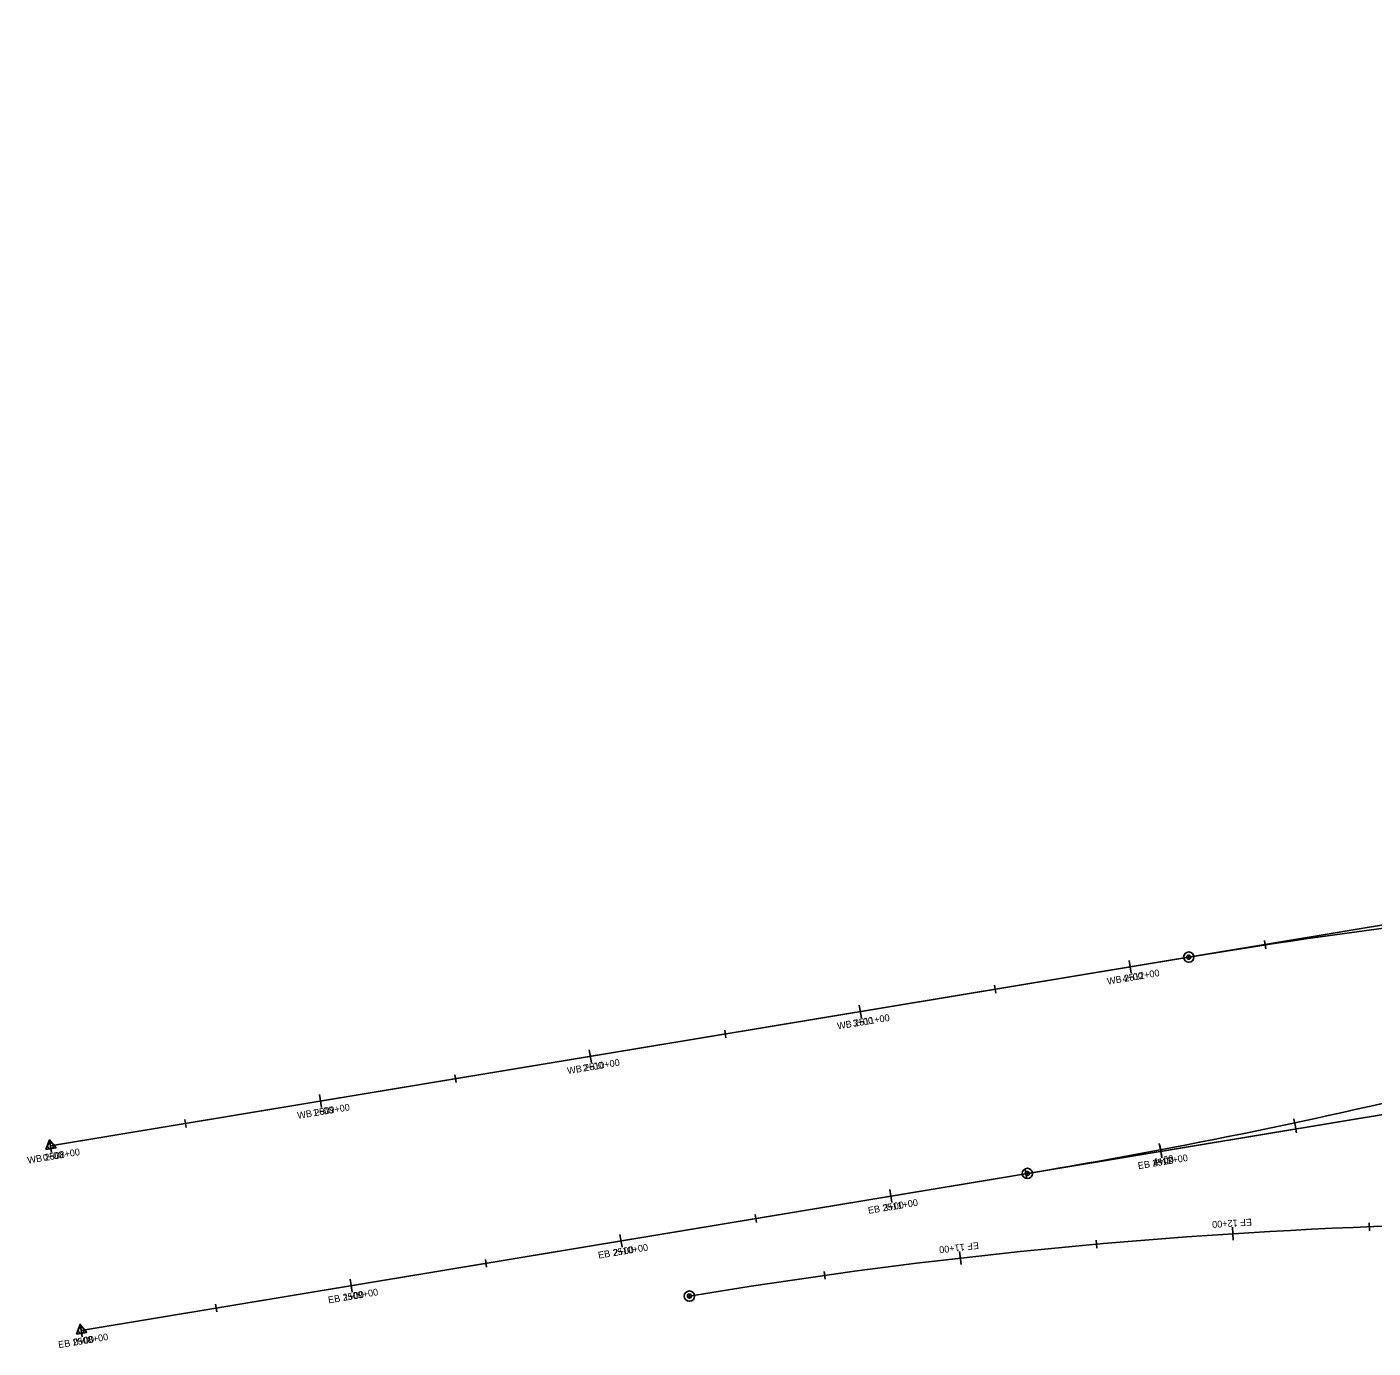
# Model space of a CAD drawing. Extents: x 950864 to 953360, y 1126381 to 1128045.
# Drawn here: x 950863.9 to 951355.9, y 1127047.3 to 1127530 of the extents above; entities that cross this region are included whole.
import ezdxf

# ---------------------------------------------------------------- set-up
doc = ezdxf.new("R2010")
doc.units = 0
for name, color, linetype in [('Existing', 7, 'Continuous'), ('LFILL_P', 7, 'Continuous'), ('North Crossover', 7, 'Continuous')]:
    doc.layers.add(name, color=color, linetype=linetype)

msp = doc.modelspace()

# ---------------------------------------------------------------- linework, layer by layer
at = {"layer": 'Existing'}
for p, q in [((950872.52, 1127121.15), (953338.85, 1127530.05)), ((950883.69, 1127053.72), (953350.03, 1127462.62))]:
    msp.add_line(p, q, dxfattribs=at)
for points in [[(951316.22, 1127196.17), (951316.69, 1127193.33)], [(951266.74, 1127188.94), (951267.52, 1127184.21)], [(951217.57, 1127179.82), (951218.04, 1127176.97)], [(951168.08, 1127172.59), (951168.87, 1127167.85)], [(951118.91, 1127163.46), (951119.38, 1127160.62)], [(951069.43, 1127156.23), (951070.21, 1127151.49)], [(951020.26, 1127147.1), (951020.73, 1127144.26)], [(950970.78, 1127139.87), (950971.56, 1127135.14)], [(950921.61, 1127130.75), (950922.08, 1127127.91)], [(951327.4, 1127128.74), (951327.87, 1127125.9)], [(950870.83, 1127119.76), (950872.16, 1127123.3)], [(950874.56, 1127120.38), (950870.83, 1127119.76)], [(950872.12, 1127123.52), (950872.91, 1127118.78)], [(950872.16, 1127123.3), (950874.56, 1127120.38)], [(951277.92, 1127121.51), (951278.7, 1127116.78)], [(951228.75, 1127112.39), (951229.22, 1127109.55)], [(951179.26, 1127105.16), (951180.05, 1127100.42)], [(951130.09, 1127096.03), (951130.56, 1127093.19)], [(951304.47, 1127091.42), (951304.77, 1127086.63)], [(951354.5, 1127093.03), (951354.61, 1127090.15)], [(951080.61, 1127088.8), (951081.39, 1127084.07)], [(951254.64, 1127086.63), (951254.9, 1127083.76)], [(951204.76, 1127082.51), (951205.3, 1127077.74)], [(951031.44, 1127079.68), (951031.91, 1127076.84)], [(950981.96, 1127072.45), (950982.74, 1127067.71)], [(951155.23, 1127075.24), (951155.63, 1127072.38)], [(950932.79, 1127063.32), (950933.26, 1127060.48)], [(950883.3, 1127056.09), (950884.09, 1127051.35)], [(950882.01, 1127052.33), (950883.34, 1127055.87)], [(950885.74, 1127052.95), (950882.01, 1127052.33)], [(950883.34, 1127055.87), (950885.74, 1127052.95)]]:
    msp.add_lwpolyline(points, dxfattribs=at)
for centre, radius in [((950872.52, 1127121.15), 1.09), ((951106.01, 1127066.25), 1.88), ((951106.01, 1127066.25), 0.747), ((951106.01, 1127066.25), 0.156), ((950883.7, 1127053.72), 1.09)]:
    msp.add_circle(centre, radius, dxfattribs=at)
msp.add_arc((951432.14, 1125099.1), 1994, 85.39079, 99.4135, dxfattribs=at)
at = {"layer": 'LFILL_P'}
for p, q in [((950872.52, 1127121.15), (951288.53, 1127190.12)), ((950883.69, 1127053.72), (951597.75, 1127172.11))]:
    msp.add_line(p, q, dxfattribs=at)
for points in [[(951316.27, 1127195.99), (951316.7, 1127193.14)], [(951266.74, 1127188.94), (951267.52, 1127184.21)], [(951217.57, 1127179.82), (951218.04, 1127176.97)], [(951168.08, 1127172.59), (951168.87, 1127167.85)], [(951118.91, 1127163.46), (951119.38, 1127160.62)], [(951069.43, 1127156.23), (951070.21, 1127151.49)], [(951020.26, 1127147.1), (951020.73, 1127144.26)], [(950970.78, 1127139.87), (950971.56, 1127135.14)], [(950921.61, 1127130.75), (950922.08, 1127127.91)], [(951327.4, 1127128.74), (951327.87, 1127125.9)], [(950870.83, 1127119.76), (950872.16, 1127123.3)], [(950874.56, 1127120.38), (950870.83, 1127119.76)], [(950872.12, 1127123.52), (950872.91, 1127118.78)], [(950872.16, 1127123.3), (950874.56, 1127120.38)], [(951277.92, 1127121.51), (951278.7, 1127116.78)], [(951228.75, 1127112.39), (951229.22, 1127109.55)], [(951179.26, 1127105.16), (951180.05, 1127100.42)], [(951130.09, 1127096.03), (951130.56, 1127093.19)], [(951080.61, 1127088.8), (951081.39, 1127084.07)], [(951031.44, 1127079.68), (951031.91, 1127076.84)], [(950981.96, 1127072.45), (950982.74, 1127067.71)], [(950932.79, 1127063.32), (950933.26, 1127060.48)], [(950883.3, 1127056.09), (950884.09, 1127051.35)], [(950882.01, 1127052.33), (950883.34, 1127055.87)], [(950885.74, 1127052.95), (950882.01, 1127052.33)], [(950883.34, 1127055.87), (950885.74, 1127052.95)]]:
    msp.add_lwpolyline(points, dxfattribs=at)
for centre, radius in [((951288.53, 1127190.12), 1.88), ((951288.53, 1127190.12), 0.747), ((951288.53, 1127190.12), 0.156), ((950872.52, 1127121.15), 1.09), ((950883.7, 1127053.72), 1.09)]:
    msp.add_circle(centre, radius, dxfattribs=at)
msp.add_arc((951642.63, 1125054.28), 2165, 90.26513, 99.4135, dxfattribs=at)
at = {"layer": 'North Crossover'}
for p, q in [((950872.52, 1127121.15), (951607.23, 1127242.96)), ((950883.69, 1127053.72), (951229.53, 1127111.06))]:
    msp.add_line(p, q, dxfattribs=at)
for points in [[(951316.22, 1127196.17), (951316.69, 1127193.33)], [(951266.74, 1127188.94), (951267.52, 1127184.21)], [(951217.57, 1127179.82), (951218.04, 1127176.97)], [(951168.08, 1127172.59), (951168.87, 1127167.85)], [(951118.91, 1127163.46), (951119.38, 1127160.62)], [(951069.43, 1127156.23), (951070.21, 1127151.49)], [(951020.26, 1127147.1), (951020.73, 1127144.26)], [(950970.78, 1127139.87), (950971.56, 1127135.14)], [(950921.61, 1127130.75), (950922.08, 1127127.91)], [(951326.93, 1127130.98), (951327.53, 1127128.16)], [(950870.83, 1127119.76), (950872.16, 1127123.3)], [(950874.56, 1127120.38), (950870.83, 1127119.76)], [(950872.12, 1127123.52), (950872.91, 1127118.78)], [(950872.16, 1127123.3), (950874.56, 1127120.38)], [(951277.76, 1127122.06), (951278.66, 1127117.34)], [(951228.75, 1127112.39), (951229.22, 1127109.55)], [(951179.26, 1127105.16), (951180.05, 1127100.42)], [(951130.09, 1127096.03), (951130.56, 1127093.19)], [(951080.61, 1127088.8), (951081.39, 1127084.07)], [(951031.44, 1127079.68), (951031.91, 1127076.84)], [(950981.96, 1127072.45), (950982.74, 1127067.71)], [(950932.79, 1127063.32), (950933.26, 1127060.48)], [(950883.3, 1127056.09), (950884.09, 1127051.35)], [(950882.01, 1127052.33), (950883.34, 1127055.87)], [(950885.74, 1127052.95), (950882.01, 1127052.33)], [(950883.34, 1127055.87), (950885.74, 1127052.95)]]:
    msp.add_lwpolyline(points, dxfattribs=at)
for centre, radius in [((950872.52, 1127121.15), 1.09), ((951229.53, 1127111.06), 1.88), ((951229.53, 1127111.06), 0.747), ((951229.53, 1127111.06), 0.156), ((950883.7, 1127053.72), 1.09)]:
    msp.add_circle(centre, radius, dxfattribs=at)
msp.add_arc((950875.43, 1129246.9), 2165, 279.4135, 288.44308, dxfattribs=at)

# ---------------------------------------------------------------- texts
at = {"layer": 'Existing'}
for s, rotation, p in [('WB 2512+00', 9.4135, (951258.88, 1127180.05)), ('WB 2511+00', 9.4135, (951160.23, 1127163.69)), ('WB 2510+00', 9.4135, (951061.57, 1127147.34)), ('WB 2509+00', 9.4135, (950962.92, 1127130.98)), ('WB 2508+00', 9.4135, (950864.27, 1127114.62)), ('EB 2512+00', 9.4135, (951270.14, 1127112.63)), ('EB 2511+00', 9.4135, (951171.49, 1127096.28)), ('EF 12+00', 183.6667, (951311.52, 1127094.56)), ('EF 11+00', 186.5401, (951211.64, 1127086.01)), ('EB 2510+00', 9.4135, (951072.84, 1127079.92)), ('EB 2509+00', 9.4135, (950974.18, 1127063.57)), ('EB 2508+00', 9.4135, (950875.53, 1127047.21))]:
    msp.add_text(s, height=2.496, rotation=rotation, dxfattribs=at).set_placement(p)
at = {"layer": 'LFILL_P'}
for s, p in [('4+00', (951264.55, 1127180.99)), ('3+00', (951165.93, 1127164.64)), ('2+00', (951067.24, 1127148.28)), ('1+00', (950968.59, 1127131.92)), ('0+00', (950869.94, 1127115.56)), ('4+00', (951275.73, 1127113.56)), ('3+00', (951177.11, 1127097.21)), ('2+00', (951078.42, 1127080.85)), ('1+00', (950979.77, 1127064.49)), ('0+00', (950881.11, 1127048.14))]:
    msp.add_text(s, height=2.496, rotation=9.4135, dxfattribs=at).set_placement(p)
at = {"layer": 'North Crossover'}
for s, rotation, p in [('4+00', 9.4135, (951264.55, 1127180.99)), ('3+00', 9.4135, (951165.93, 1127164.64)), ('2+00', 9.4135, (951067.24, 1127148.28)), ('1+00', 9.4135, (950968.59, 1127131.92)), ('0+00', 9.4135, (950869.94, 1127115.56)), ('4+00', 10.722, (951275.76, 1127114.06)), ('3+00', 9.4135, (951177.11, 1127097.21)), ('2+00', 9.4135, (951078.42, 1127080.85)), ('1+00', 9.4135, (950979.77, 1127064.49)), ('0+00', 9.4135, (950881.11, 1127048.14))]:
    msp.add_text(s, height=2.496, rotation=rotation, dxfattribs=at).set_placement(p)

doc.saveas('drawing.dxf')
